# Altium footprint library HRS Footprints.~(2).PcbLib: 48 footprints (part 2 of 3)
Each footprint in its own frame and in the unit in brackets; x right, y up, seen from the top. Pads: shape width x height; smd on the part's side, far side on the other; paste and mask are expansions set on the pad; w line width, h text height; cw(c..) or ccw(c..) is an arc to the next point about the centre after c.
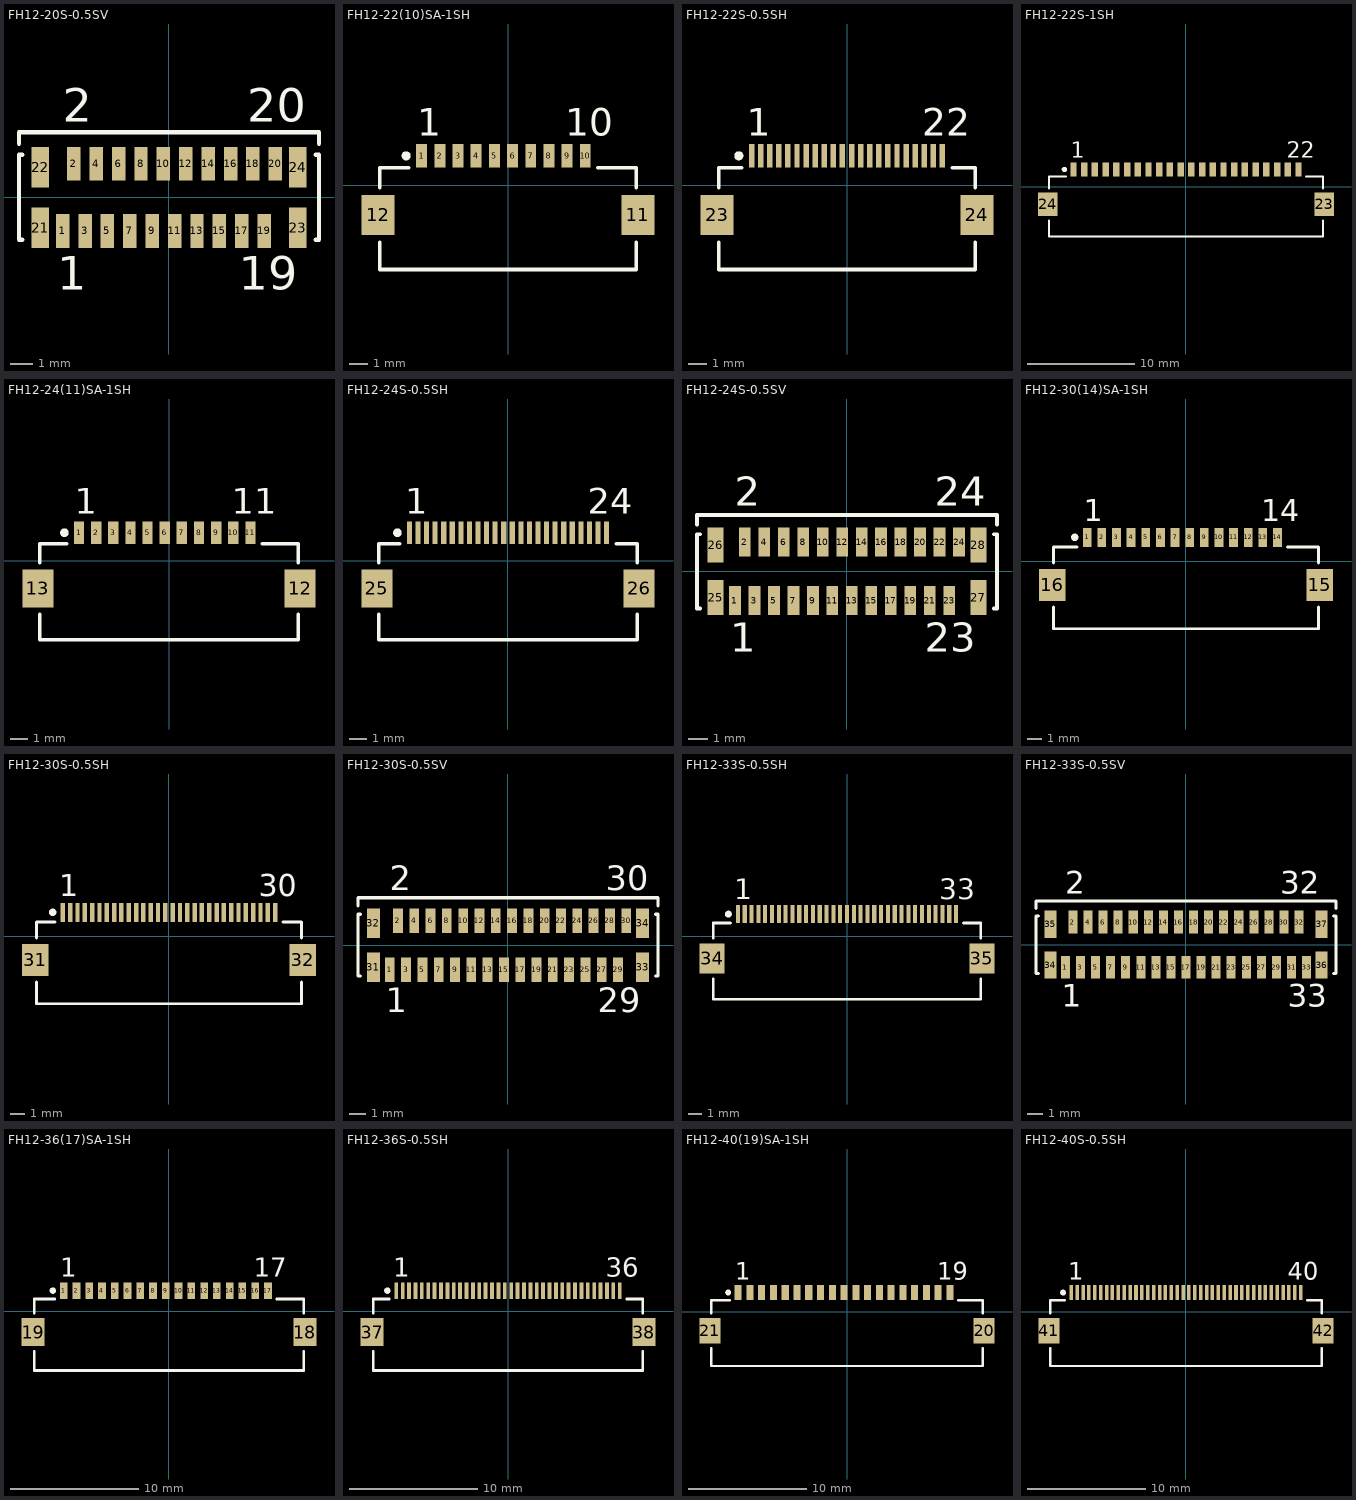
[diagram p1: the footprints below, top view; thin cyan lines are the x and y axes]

## FH12-20S-0.5SV [mm] "Connector; FH12 Series; 20 Position; 0.5mm Spaced Vertical Mounting"
height 4.85
pads (24):
  rect 0.6x1.5 smd: 1(-4.75,-1.5) 2(-4.25,1.5) 3(-3.75,-1.5) 4(-3.25,1.5) 5(-2.75,-1.5) 6(-2.25,1.5) 7(-1.75,-1.5) 8(-1.25,1.5) 9(-0.75,-1.5) 10(-0.25,1.5) 11(0.25,-1.5) 12(0.75,1.5) 13(1.25,-1.5) 14(1.75,1.5) 15(2.25,-1.5) 16(2.75,1.5) 17(3.25,-1.5) 18(3.75,1.5) 19(4.25,-1.5) 20(4.75,1.5)
  rect 0.8x1.8 smd: 21(-5.75,-1.35) 22(-5.75,1.35) 23(5.75,-1.35) 24(5.75,1.35)
Top Overlay:
  lines w0.2: -6.7,2.4 -6.7,2.9 6.7,2.9 6.7,2.4 ; -6.55,-1.9 -6.7,-1.9 -6.7,1.9 -6.55,1.9 ; 6.55,-1.9 6.7,-1.9 6.7,1.9 6.55,1.9
  text "19" at 3.125,-4.125 h1.5
  text "20" at 3.5,3.375 h1.5
  text "2" at -4.75,3.375 h1.5
  text "1" at -5,-4.125 h1.5

## FH12-22(10)SA-1SH [mm] "Connector; FH12 Series; 10 Position; 1.0mm Spaced Bottom Eccentric Contact"
height 2
pads (12):
  rect 0.6x1.3 smd: 1(-4.75,1.625) 2(-3.75,1.625) 3(-2.75,1.625) 4(-1.75,1.625) 5(-0.75,1.625) 6(0.25,1.625) 7(1.25,1.625) 8(2.25,1.625) 9(3.25,1.625) 10(4.25,1.625)
  rect 1.8x2.2 smd: 11(7.15,-1.625) 12(-7.15,-1.625)
Top Overlay:
  circle w0.25: c-5.6,1.625 r0.125
  lines w0.2: -7.05,-3.125 -7.05,-4.625 7.05,-4.625 7.05,-3.125 ; -7.05,-0.125 -7.05,0.975 -5.45,0.975 ; 4.95,0.975 7.05,0.975 7.05,-0.125
  text "10" at 3.15,2.725 h1.5
  text "1" at -5,2.725 h1.5

## FH12-22S-0.5SH [mm] "Connector; FH12 Series; 22 Position; 0.5mm Spaced Bottom Contact"
height 2
pads (24):
  rect 0.3x1.3 smd: 1(-5.25,1.625) 2(-4.75,1.625) 3(-4.25,1.625) 4(-3.75,1.625) 5(-3.25,1.625) 6(-2.75,1.625) 7(-2.25,1.625) 8(-1.75,1.625) 9(-1.25,1.625) 10(-0.75,1.625) 11(-0.25,1.625) 12(0.25,1.625) 13(0.75,1.625) 14(1.25,1.625) 15(1.75,1.625) 16(2.25,1.625) 17(2.75,1.625) 18(3.25,1.625) 19(3.75,1.625) 20(4.25,1.625) 21(4.75,1.625) 22(5.25,1.625)
  rect 1.8x2.2 smd: 23(-7.15,-1.625) 24(7.15,-1.625)
Top Overlay:
  circle w0.25: c-5.95,1.625 r0.125
  lines w0.2: -7.05,-3.125 -7.05,-4.625 7.05,-4.625 7.05,-3.125 ; -7.05,-0.125 -7.05,0.975 -5.8,0.975 ; 5.8,0.975 7.05,0.975 7.05,-0.125
  text "1" at -5.5,2.725 h1.5
  text "22" at 4.15,2.725 h1.5

## FH12-22S-1SH [mm] "Connector; FH12 Series; 22 Position; 1.0mm Spaced Bottom Standard Contact"
height 2
pads (24):
  rect 0.6x1.3 smd: 1(-10.5,1.625) 2(-9.5,1.625) 3(-8.5,1.625) 4(-7.5,1.625) 5(-6.5,1.625) 6(-5.5,1.625) 7(-4.5,1.625) 8(-3.5,1.625) 9(-2.5,1.625) 10(-1.5,1.625) 11(-0.5,1.625) 12(0.5,1.625) 13(1.5,1.625) 14(2.5,1.625) 15(3.5,1.625) 16(4.5,1.625) 17(5.5,1.625) 18(6.5,1.625) 19(7.5,1.625) 20(8.5,1.625) 21(9.5,1.625) 22(10.5,1.625)
  rect 1.8x2.2 smd: 23(12.9,-1.625) 24(-12.9,-1.625)
Top Overlay:
  circle w0.25: c-11.35,1.625 r0.125
  lines w0.2: -12.8,-3.125 -12.8,-4.625 12.8,-4.625 12.8,-3.125 ; -12.8,-0.125 -12.8,0.975 -11.2,0.975 ; 11.2,0.975 12.8,0.975 12.8,-0.125
  text "1" at -10.75,2.725 h1.5
  text "22" at 9.4,2.725 h1.5

## FH12-24(11)SA-1SH [mm] "Connector; FH12 Series; 11 Position; 1.0mm Spaced Bottom Eccentric Contact"
height 2
pads (13):
  rect 0.6x1.3 smd: 1(-5.25,1.625) 2(-4.25,1.625) 3(-3.25,1.625) 4(-2.25,1.625) 5(-1.25,1.625) 6(-0.25,1.625) 7(0.75,1.625) 8(1.75,1.625) 9(2.75,1.625) 10(3.75,1.625) 11(4.75,1.625)
  rect 1.8x2.2 smd: 12(7.65,-1.625) 13(-7.65,-1.625)
Top Overlay:
  circle w0.25: c-6.1,1.625 r0.125
  lines w0.2: -7.55,-3.125 -7.55,-4.625 7.55,-4.625 7.55,-3.125 ; -7.55,-0.125 -7.55,0.975 -5.95,0.975 ; 5.45,0.975 7.55,0.975 7.55,-0.125
  text "11" at 3.65,2.725 h1.5
  text "1" at -5.5,2.725 h1.5

## FH12-24S-0.5SH [mm] "Connector; FH12 Series; 24 Position; 0.5mm Spaced Bottom Contact"
height 2
pads (26):
  rect 0.3x1.3 smd: 1(-5.75,1.625) 2(-5.25,1.625) 3(-4.75,1.625) 4(-4.25,1.625) 5(-3.75,1.625) 6(-3.25,1.625) 7(-2.75,1.625) 8(-2.25,1.625) 9(-1.75,1.625) 10(-1.25,1.625) 11(-0.75,1.625) 12(-0.25,1.625) 13(0.25,1.625) 14(0.75,1.625) 15(1.25,1.625) 16(1.75,1.625) 17(2.25,1.625) 18(2.75,1.625) 19(3.25,1.625) 20(3.75,1.625) 21(4.25,1.625) 22(4.75,1.625) 23(5.25,1.625) 24(5.75,1.625)
  rect 1.8x2.2 smd: 25(-7.65,-1.625) 26(7.65,-1.625)
Top Overlay:
  circle w0.25: c-6.45,1.625 r0.125
  lines w0.2: -7.55,-3.125 -7.55,-4.625 7.55,-4.625 7.55,-3.125 ; -7.55,-0.125 -7.55,0.975 -6.3,0.975 ; 6.3,0.975 7.55,0.975 7.55,-0.125
  text "24" at 4.65,2.725 h1.5
  text "1" at -6,2.725 h1.5

## FH12-24S-0.5SV [mm] "Connector; FH12 Series; 24 Position; 0.5mm Spaced Vertical Mounting"
height 4.85
pads (28):
  rect 0.6x1.5 smd: 1(-5.75,-1.5) 2(-5.25,1.5) 3(-4.75,-1.5) 4(-4.25,1.5) 5(-3.75,-1.5) 6(-3.25,1.5) 7(-2.75,-1.5) 8(-2.25,1.5) 9(-1.75,-1.5) 10(-1.25,1.5) 11(-0.75,-1.5) 12(-0.25,1.5) 13(0.25,-1.5) 14(0.75,1.5) 15(1.25,-1.5) 16(1.75,1.5) 17(2.25,-1.5) 18(2.75,1.5) 19(3.25,-1.5) 20(3.75,1.5) 21(4.25,-1.5) 22(4.75,1.5) 23(5.25,-1.5) 24(5.75,1.5)
  rect 0.8x1.8 smd: 25(-6.75,-1.35) 26(-6.75,1.35) 27(6.75,-1.35) 28(6.75,1.35)
Top Overlay:
  lines w0.2: -7.7,2.4 -7.7,2.9 7.7,2.9 7.7,2.4 ; -7.55,-1.9 -7.7,-1.9 -7.7,1.9 -7.55,1.9 ; 7.55,-1.9 7.7,-1.9 7.7,1.9 7.55,1.9
  text "1" at -6,-4.125 h1.5
  text "2" at -5.75,3.375 h1.5
  text "24" at 4.5,3.375 h1.5
  text "23" at 4,-4.125 h1.5

## FH12-30(14)SA-1SH [mm] "Connector; FH12 Series; 14 Position; 1.0mm Spaced Bottom Eccentric Contact"
height 2
pads (16):
  rect 0.6x1.3 smd: 1(-6.75,1.625) 2(-5.75,1.625) 3(-4.75,1.625) 4(-3.75,1.625) 5(-2.75,1.625) 6(-1.75,1.625) 7(-0.75,1.625) 8(0.25,1.625) 9(1.25,1.625) 10(2.25,1.625) 11(3.25,1.625) 12(4.25,1.625) 13(5.25,1.625) 14(6.25,1.625)
  rect 1.8x2.2 smd: 15(9.15,-1.625) 16(-9.15,-1.625)
Top Overlay:
  circle w0.25: c-7.6,1.625 r0.125
  lines w0.2: -9.05,-3.125 -9.05,-4.625 9.05,-4.625 9.05,-3.125 ; -9.05,-0.125 -9.05,0.975 -7.45,0.975 ; 6.95,0.975 9.05,0.975 9.05,-0.125
  text "14" at 5.15,2.725 h1.5
  text "1" at -7,2.725 h1.5

## FH12-30S-0.5SH [mm] "Connector; FH12 Series; 30 Position; 0.5mm Spaced Bottom Contact"
height 2
pads (32):
  rect 0.3x1.3 smd: 1(-7.25,1.625) 2(-6.75,1.625) 3(-6.25,1.625) 4(-5.75,1.625) 5(-5.25,1.625) 6(-4.75,1.625) 7(-4.25,1.625) 8(-3.75,1.625) 9(-3.25,1.625) 10(-2.75,1.625) 11(-2.25,1.625) 12(-1.75,1.625) 13(-1.25,1.625) 14(-0.75,1.625) 15(-0.25,1.625) 16(0.25,1.625) 17(0.75,1.625) 18(1.25,1.625) 19(1.75,1.625) 20(2.25,1.625) 21(2.75,1.625) 22(3.25,1.625) 23(3.75,1.625) 24(4.25,1.625) 25(4.75,1.625) 26(5.25,1.625) 27(5.75,1.625) 28(6.25,1.625) 29(6.75,1.625) 30(7.25,1.625)
  rect 1.8x2.2 smd: 31(-9.15,-1.625) 32(9.15,-1.625)
Top Overlay:
  circle w0.25: c-7.95,1.625 r0.125
  lines w0.2: -9.05,-3.125 -9.05,-4.625 9.05,-4.625 9.05,-3.125 ; -9.05,-0.125 -9.05,0.975 -7.8,0.975 ; 7.8,0.975 9.05,0.975 9.05,-0.125
  text "1" at -7.5,2.725 h1.5
  text "30" at 6.15,2.725 h1.5

## FH12-30S-0.5SV [mm] "Connector; FH12 Series; 30 Position; 0.5mm Spaced Vertical Mounting"
height 4.85
pads (34):
  rect 0.6x1.5 smd: 1(-7.25,-1.5) 2(-6.75,1.5) 3(-6.25,-1.5) 4(-5.75,1.5) 5(-5.25,-1.5) 6(-4.75,1.5) 7(-4.25,-1.5) 8(-3.75,1.5) 9(-3.25,-1.5) 10(-2.75,1.5) 11(-2.25,-1.5) 12(-1.75,1.5) 13(-1.25,-1.5) 14(-0.75,1.5) 15(-0.25,-1.5) 16(0.25,1.5) 17(0.75,-1.5) 18(1.25,1.5) 19(1.75,-1.5) 20(2.25,1.5) 21(2.75,-1.5) 22(3.25,1.5) 23(3.75,-1.5) 24(4.25,1.5) 25(4.75,-1.5) 26(5.25,1.5) 27(5.75,-1.5) 28(6.25,1.5) 29(6.75,-1.5) 30(7.25,1.5)
  rect 0.8x1.8 smd: 31(-8.25,-1.35) 32(-8.25,1.35) 33(8.25,-1.35) 34(8.25,1.35)
Top Overlay:
  lines w0.2: -9.2,2.4 -9.2,2.9 9.2,2.9 9.2,2.4 ; -9.05,-1.9 -9.2,-1.9 -9.2,1.9 -9.05,1.9 ; 9.05,-1.9 9.2,-1.9 9.2,1.9 9.05,1.9
  text "1" at -7.5,-4.125 h1.5
  text "30" at 6,3.375 h1.5
  text "2" at -7.25,3.375 h1.5
  text "29" at 5.5,-4.125 h1.5

## FH12-33S-0.5SH [mm] "Connector; FH12 Series; 33 Position; 0.5mm Spaced Bottom Contact"
height 2
pads (35):
  rect 0.3x1.3 smd: 1(-8,1.625) 2(-7.5,1.625) 3(-7,1.625) 4(-6.5,1.625) 5(-6,1.625) 6(-5.5,1.625) 7(-5,1.625) 8(-4.5,1.625) 9(-4,1.625) 10(-3.5,1.625) 11(-3,1.625) 12(-2.5,1.625) 13(-2,1.625) 14(-1.5,1.625) 15(-1,1.625) 16(-0.5,1.625) 17(0,1.625) 18(0.5,1.625) 19(1,1.625) 20(1.5,1.625) 21(2,1.625) 22(2.5,1.625) 23(3,1.625) 24(3.5,1.625) 25(4,1.625) 26(4.5,1.625) 27(5,1.625) 28(5.5,1.625) 29(6,1.625) 30(6.5,1.625) 31(7,1.625) 32(7.5,1.625) 33(8,1.625)
  rect 1.8x2.2 smd: 34(-9.9,-1.625) 35(9.9,-1.625)
Top Overlay:
  circle w0.25: c-8.7,1.625 r0.125
  lines w0.2: -9.8,-3.125 -9.8,-4.625 9.8,-4.625 9.8,-3.125 ; -9.8,-0.125 -9.8,0.975 -8.55,0.975 ; 8.55,0.975 9.8,0.975 9.8,-0.125
  text "33" at 6.75,2.725 h1.5
  text "1" at -8.25,2.725 h1.5

## FH12-33S-0.5SV [mm] "Connector; FH12 Series; 33 Position; 0.5mm Spaced Vertical Mounting"
height 4.85
pads (37):
  rect 0.6x1.5 smd: 1(-8,-1.5) 2(-7.5,1.5) 3(-7,-1.5) 4(-6.5,1.5) 5(-6,-1.5) 6(-5.5,1.5) 7(-5,-1.5) 8(-4.5,1.5) 9(-4,-1.5) 10(-3.5,1.5) 11(-3,-1.5) 12(-2.5,1.5) 13(-2,-1.5) 14(-1.5,1.5) 15(-1,-1.5) 16(-0.5,1.5) 17(0,-1.5) 18(0.5,1.5) 19(1,-1.5) 20(1.5,1.5) 21(2,-1.5) 22(2.5,1.5) 23(3,-1.5) 24(3.5,1.5) 25(4,-1.5) 26(4.5,1.5) 27(5,-1.5) 28(5.5,1.5) 29(6,-1.5) 30(6.5,1.5) 31(7,-1.5) 32(7.5,1.5) 33(8,-1.5)
  rect 0.8x1.8 smd: 34(-9,-1.35) 35(-9,1.35) 36(9,-1.35) 37(9,1.35)
Top Overlay:
  lines w0.2: -9.95,2.4 -9.95,2.9 9.95,2.9 9.95,2.4 ; -9.8,-1.9 -9.95,-1.9 -9.95,1.9 -9.8,1.9 ; 9.8,-1.9 9.95,-1.9 9.95,1.9 9.8,1.9
  text "33" at 6.75,-4.125 h1.5
  text "1" at -8.25,-4.125 h1.5
  text "2" at -8,3.375 h1.5
  text "32" at 6.25,3.375 h1.5

## FH12-36(17)SA-1SH [mm] "Connector; FH12 Series; 17 Position; 1.0mm Spaced Bottom Eccentric Contact"
height 2
pads (19):
  rect 0.6x1.3 smd: 1(-8.25,1.625) 2(-7.25,1.625) 3(-6.25,1.625) 4(-5.25,1.625) 5(-4.25,1.625) 6(-3.25,1.625) 7(-2.25,1.625) 8(-1.25,1.625) 9(-0.25,1.625) 10(0.75,1.625) 11(1.75,1.625) 12(2.75,1.625) 13(3.75,1.625) 14(4.75,1.625) 15(5.75,1.625) 16(6.75,1.625) 17(7.75,1.625)
  rect 1.8x2.2 smd: 18(10.65,-1.625) 19(-10.65,-1.625)
Top Overlay:
  circle w0.25: c-9.1,1.625 r0.125
  lines w0.2: -10.55,-3.125 -10.55,-4.625 10.55,-4.625 10.55,-3.125 ; -10.55,-0.125 -10.55,0.975 -8.95,0.975 ; 8.45,0.975 10.55,0.975 10.55,-0.125
  text "17" at 6.65,2.725 h1.5
  text "1" at -8.5,2.725 h1.5

## FH12-36S-0.5SH [mm] "Connector; FH12 Series; 36 Position; 0.5mm Spaced Bottom Contact"
height 2
pads (38):
  rect 0.3x1.3 smd: 1(-8.75,1.625) 2(-8.25,1.625) 3(-7.75,1.625) 4(-7.25,1.625) 5(-6.75,1.625) 6(-6.25,1.625) 7(-5.75,1.625) 8(-5.25,1.625) 9(-4.75,1.625) 10(-4.25,1.625) 11(-3.75,1.625) 12(-3.25,1.625) 13(-2.75,1.625) 14(-2.25,1.625) 15(-1.75,1.625) 16(-1.25,1.625) 17(-0.75,1.625) 18(-0.25,1.625) 19(0.25,1.625) 20(0.75,1.625) 21(1.25,1.625) 22(1.75,1.625) 23(2.25,1.625) 24(2.75,1.625) 25(3.25,1.625) 26(3.75,1.625) 27(4.25,1.625) 28(4.75,1.625) 29(5.25,1.625) 30(5.75,1.625) 31(6.25,1.625) 32(6.75,1.625) 33(7.25,1.625) 34(7.75,1.625) 35(8.25,1.625) 36(8.75,1.625)
  rect 1.8x2.2 smd: 37(-10.65,-1.625) 38(10.65,-1.625)
Top Overlay:
  circle w0.25: c-9.45,1.625 r0.125
  lines w0.2: -10.55,-3.125 -10.55,-4.625 10.55,-4.625 10.55,-3.125 ; -10.55,-0.125 -10.55,0.975 -9.3,0.975 ; 9.3,0.975 10.55,0.975 10.55,-0.125
  text "36" at 7.65,2.725 h1.5
  text "1" at -9,2.725 h1.5

## FH12-40(19)SA-1SH [mm] "Connector; FH12 Series; 19 Position; 1.0mm Spaced Bottom Eccentric Contact"
height 2
pads (21):
  rect 0.6x1.3 smd: 1(-9.25,1.625) 2(-8.25,1.625) 3(-7.25,1.625) 4(-6.25,1.625) 5(-5.25,1.625) 6(-4.25,1.625) 7(-3.25,1.625) 8(-2.25,1.625) 9(-1.25,1.625) 10(-0.25,1.625) 11(0.75,1.625) 12(1.75,1.625) 13(2.75,1.625) 14(3.75,1.625) 15(4.75,1.625) 16(5.75,1.625) 17(6.75,1.625) 18(7.75,1.625) 19(8.75,1.625)
  rect 1.8x2.2 smd: 20(11.65,-1.625) 21(-11.65,-1.625)
Top Overlay:
  circle w0.25: c-10.1,1.625 r0.125
  lines w0.2: -11.55,-3.125 -11.55,-4.625 11.55,-4.625 11.55,-3.125 ; -11.55,-0.125 -11.55,0.975 -9.95,0.975 ; 9.45,0.975 11.55,0.975 11.55,-0.125
  text "1" at -9.5,2.725 h1.5
  text "19" at 7.65,2.725 h1.5

## FH12-40S-0.5SH [mm] "Connector; FH12 Series; 40 Position; 0.5mm Spaced Bottom Contact"
height 2
pads (42):
  rect 0.3x1.3 smd: 1(-9.75,1.625) 2(-9.25,1.625) 3(-8.75,1.625) 4(-8.25,1.625) 5(-7.75,1.625) 6(-7.25,1.625) 7(-6.75,1.625) 8(-6.25,1.625) 9(-5.75,1.625) 10(-5.25,1.625) 11(-4.75,1.625) 12(-4.25,1.625) 13(-3.75,1.625) 14(-3.25,1.625) 15(-2.75,1.625) 16(-2.25,1.625) 17(-1.75,1.625) 18(-1.25,1.625) 19(-0.75,1.625) 20(-0.25,1.625) 21(0.25,1.625) 22(0.75,1.625) 23(1.25,1.625) 24(1.75,1.625) 25(2.25,1.625) 26(2.75,1.625) 27(3.25,1.625) 28(3.75,1.625) 29(4.25,1.625) 30(4.75,1.625) 31(5.25,1.625) 32(5.75,1.625) 33(6.25,1.625) 34(6.75,1.625) 35(7.25,1.625) 36(7.75,1.625) 37(8.25,1.625) 38(8.75,1.625) 39(9.25,1.625) 40(9.75,1.625)
  rect 1.8x2.2 smd: 41(-11.65,-1.625) 42(11.65,-1.625)
Top Overlay:
  circle w0.25: c-10.45,1.625 r0.125
  lines w0.2: -11.55,-3.125 -11.55,-4.625 11.55,-4.625 11.55,-3.125 ; -11.55,-0.125 -11.55,0.975 -10.3,0.975 ; 10.3,0.975 11.55,0.975 11.55,-0.125
  text "40" at 8.65,2.725 h1.5
  text "1" at -10,2.725 h1.5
